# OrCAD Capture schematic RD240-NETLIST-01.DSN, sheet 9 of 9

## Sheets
9 1: size A3
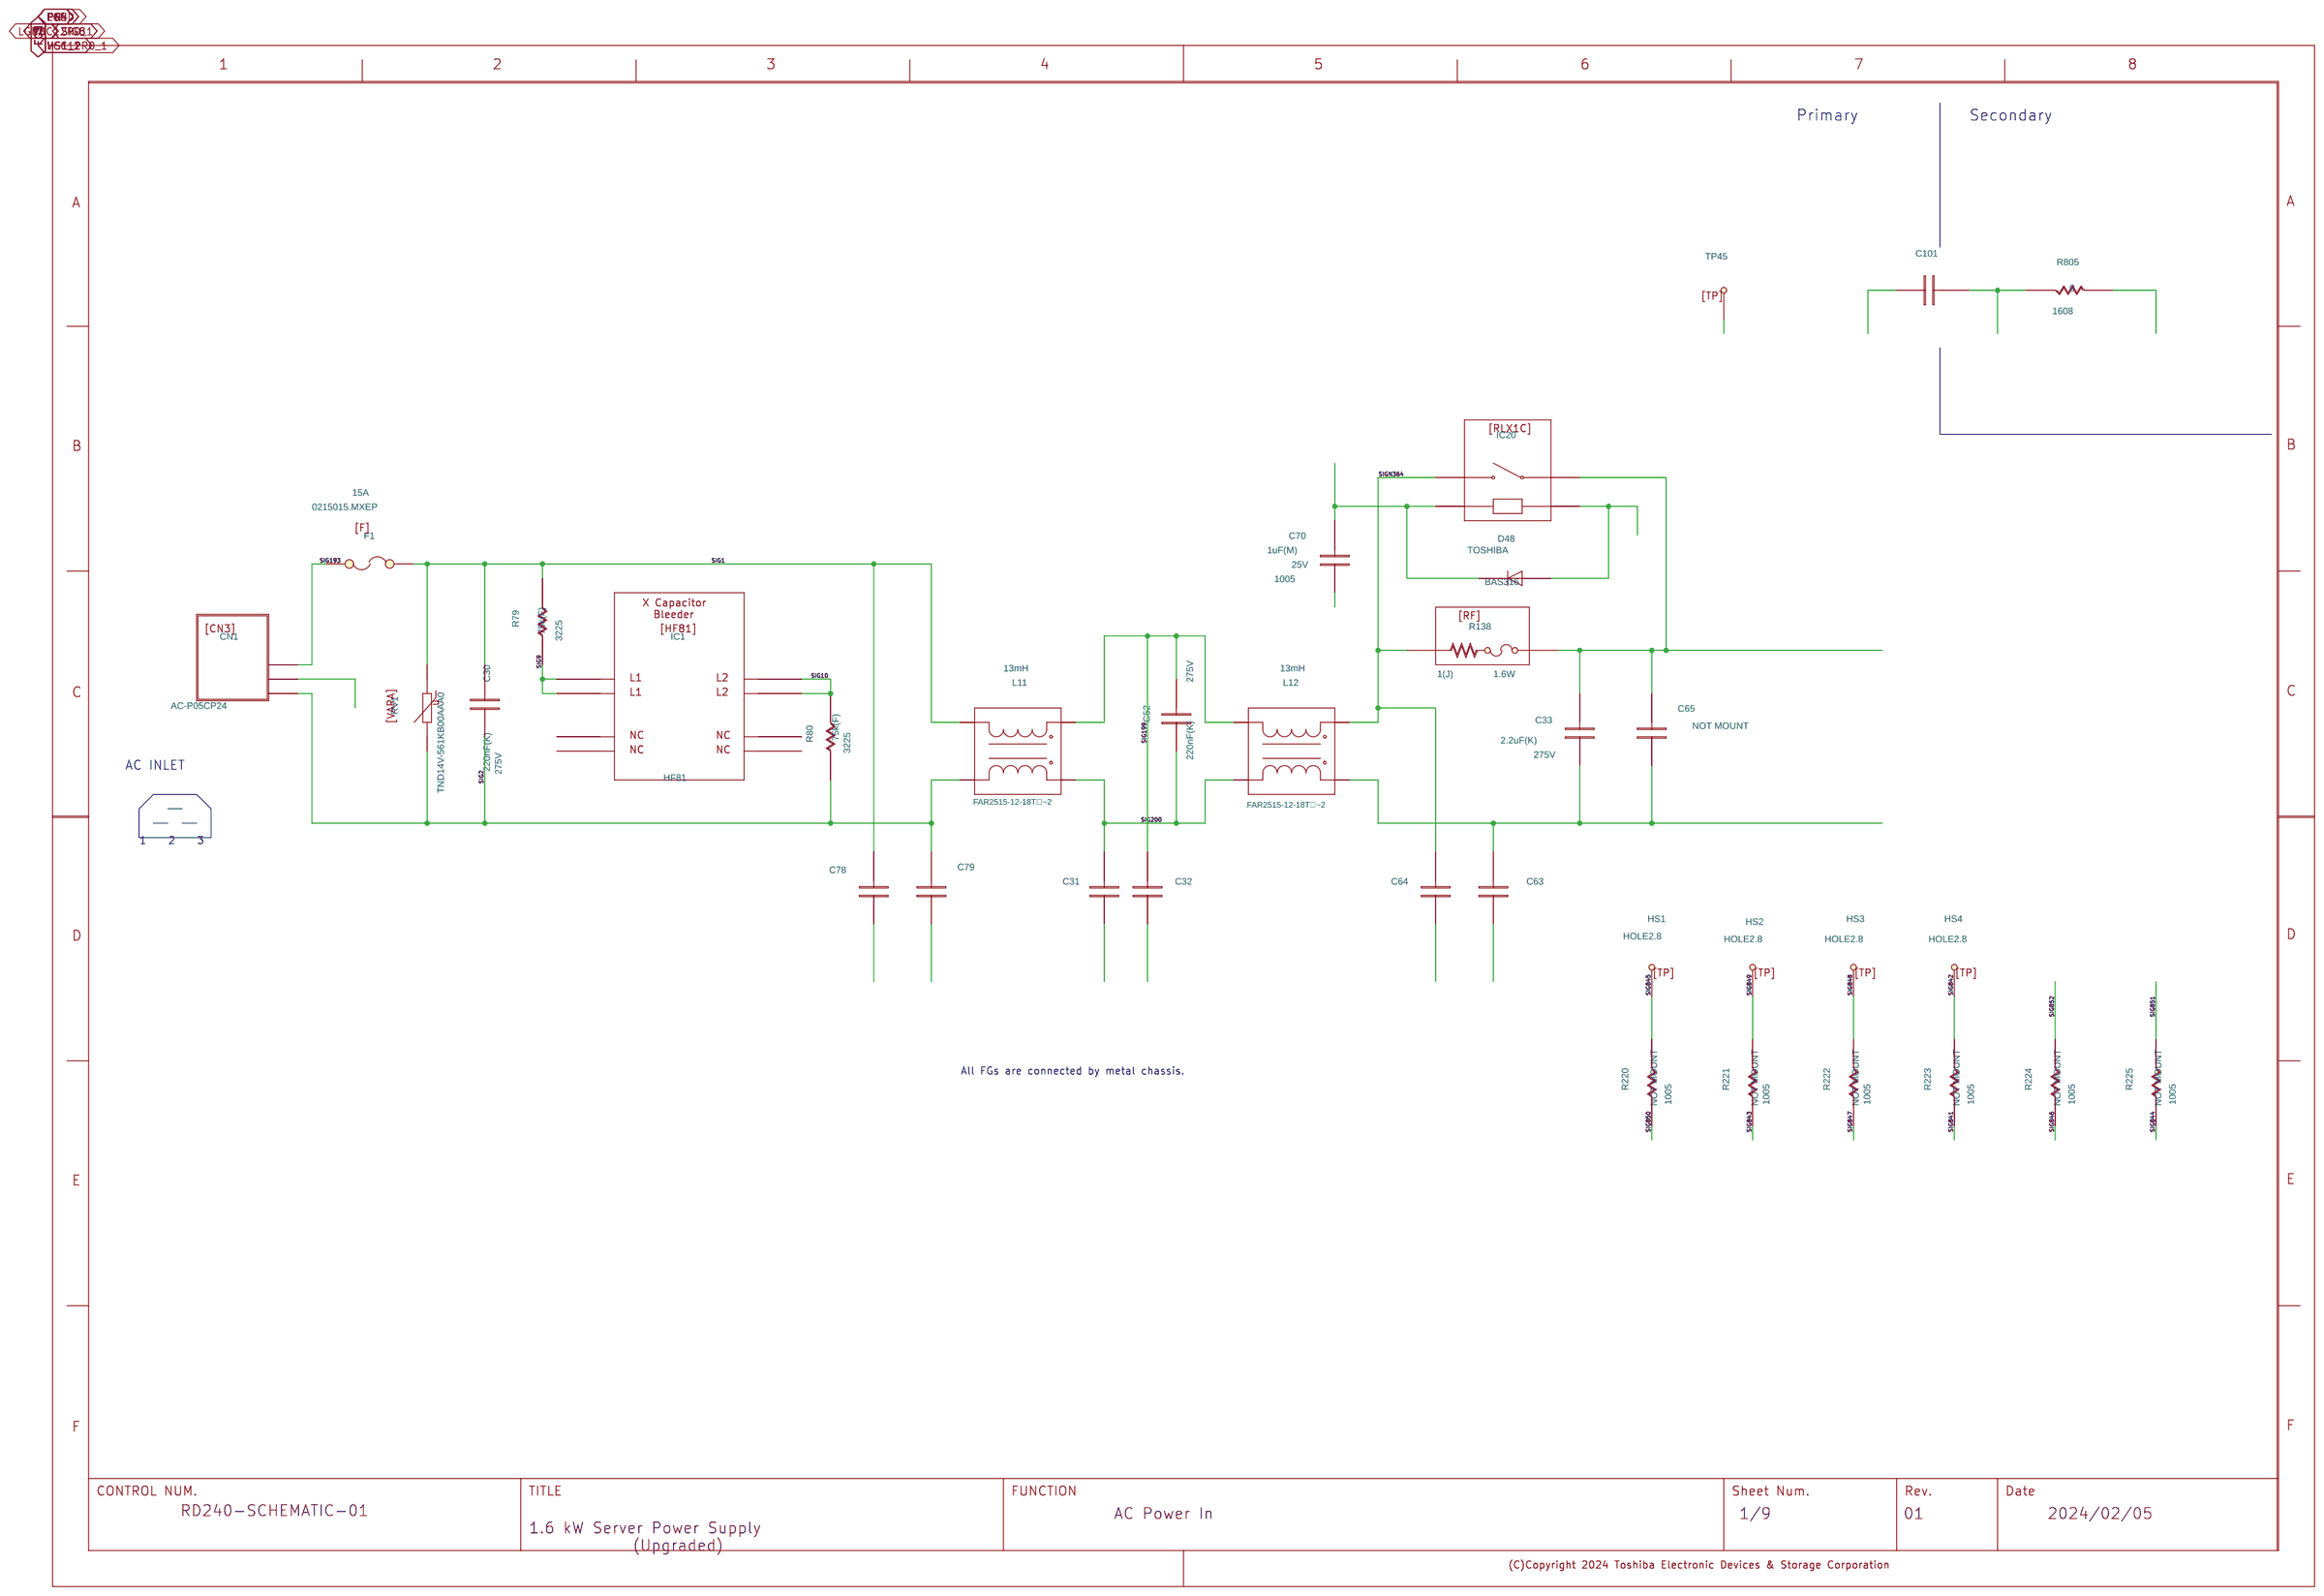
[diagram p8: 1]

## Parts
C30  C
C31  DE2E3SA222MN3AT02F
C32  DE2E3SA222MN3AT02F
C33  C
C52  C
C63  DE2E3SA222MN3AT02F
C64  DE2E3SA222MN3AT02F
C65  C
C70  C
C78  DE2B3SA101KA3BT02F
C79  DE2B3SA101KA3BT02F
C101  DE2B3SA221KA3BT02F
CN1  CN3
D48  D
F1  F
HS1  TP
HS2  TP
HS3  TP
HS4  TP
IC1  L81
IC20  G5PZ_1A
L11  HM_DLWHN6702
L12  HM_DLWHN6702
R79  R
R80  R
R138  A5MC_100JK_L3_5
R220  R
R221  R
R222  R
R223  R
R224  R
R225  R
R805  R
RV1  VARA
TP45  TP
U?#8  WAKU_DEF100

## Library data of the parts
C30 = C: AUTHOR: sptcae13; CAPACITANCETOLE: M; COMP: PRT_17; COMPONENTTYPE: 4; DATE: 2024/01/31; FNLEADFREETHET1GT2GMCTH1: N_N_N; GCOUNT: 1; INSTANCENAME: cmp241; MAKER: OKAYA; MAXGCOUNT: 1; NOMINALCAPACITA: 220n; OUMECLASSIFICATION: ƒtƒBƒ‹ƒƒRƒ“ƒfƒ“ƒT; OUMEMAKER: NIS ƒjƒbƒZƒC“d‹@; OUMEMAKERKATAMEI: R40KI322000**M; QUADMODEL: CON_220N; RATEDVOLTAGE: 275; SAVECOUNT: 0; SIZECODESMD: DIP; TIME: 13:58:26; UPDATEDATE: 2024/01/31; UPDATETIME: 13:58:26; UPDATEUSER: sptcae13; VAL1: 220nF(K); VAL2: 275V; VAL3: LE224-M
C31 = DE2E3SA222MN3AT02F: ADSMODELNAME: s_DE2E3KY222MN3AM02F; ALLGREEN: N:¢²¸; CAPACITANCETOLE: M; CDMASTERCADCELG: SIK0018; CHIPSIZE: [hsb`7.5mmió]; COMPONENTTYPE: 4; FNAPPROVALRESUG: 0:”­”Ô‚Ì‚Ý; FNCANCELLATIONG: 0:Žg—p‰Â; FNENVIRONMANTRG: N:¢²¸; FNLEADFREETHET1GT2GMCTH1: N_N_N; GCOUNT: 1; INSTANCENAME: cmp205; MAKER: MURATA; MAXGCOUNT: 1; NOMINALCAPACITA: 2.2n; OUMECLASSIFICATION: ƒZƒ‰ƒ~ƒbƒNƒRƒ“ƒfƒ“ƒT; OUMEMAKER: MRT ºc»ì; OUMEMAKERKATAMEI: DE2E3KY222MN3AM02F; OUMEPARTTYPE: C; PMPRODUCTSTYPEG: PC1; QUADMODEL: CON_2.2N; RATEDVOLTAGE: 250; SIZECODESMD: DIP; TEMPCHARACTERI2: E
C32 = DE2E3SA222MN3AT02F: ADSCNVFLAG: ON; ADSMODELNAME: s_DE2E3KY222MN3AM02F; ALLGREEN: N:¢²¸; CAPACITANCETOLE: M; CDMASTERCADCELG: SIK0018; CHIPSIZE: [hsb`7.5mmió]; COMPONENTTYPE: 4; FNAPPROVALRESUG: 0:”­”Ô‚Ì‚Ý; FNCANCELLATIONG: 0:Žg—p‰Â; FNENVIRONMANTRG: N:¢²¸; FNLEADFREETHET1GT2GMCTH1: N_N_N; GCOUNT: 1; ICX_PART_MODEL: CON_2.2N; INSTANCENAME: cmp206; MAKER: MURATA; MAXGCOUNT: 1; NOMINALCAPACITA: 2.2n; OUMECLASSIFICATION: ƒZƒ‰ƒ~ƒbƒNƒRƒ“ƒfƒ“ƒT; OUMEMAKER: MRT ºc»ì; OUMEMAKERKATAMEI: DE2E3KY222MN3AM02F; OUMEPARTTYPE: C; PMPRODUCTSTYPEG: PC1; QUADMODEL: CON_2.2N; RATEDVOLTAGE: 250; SIZECODESMD: DIP; SQ_PART_MODEL: CON_2.2N; TEMPCHARACTERI2: E
C33 = C: AUTHOR: sptcae13; CAPACITANCETOLE: K; CDMASTERCADCELG: DC0511; COMP: PRT_18; COMPONENTTYPE: 4; DATE: 2024/01/31; FNLEADFREETHET1GT2GMCTH1: 9_N_N; GCOUNT: 1; INSTANCENAME: cmp210; MAKER: Wurth; MAXGCOUNT: 1; NOMINALCAPACITA: 2.2u; OUMECLASSIFICATION: ƒtƒBƒ‹ƒƒRƒ“ƒfƒ“ƒT; OUMEMAKER: CHM “ú–{ƒPƒ~ƒRƒ“; OUMEMAKERKATAMEI: TACB2E225K; QUADMODEL: CON_2.2U; RATEDVOLTAGE: 250; SAVECOUNT: 0; SIZECODESMD: DIP; TIME: 13:58:26; UPDATEDATE: 2024/01/31; UPDATETIME: 13:58:26; UPDATEUSER: sptcae13; VAL1: 2.2uF(K); VAL2: 275V; VAL3: 890324026034CS
C52 = C: AUTHOR: sptcae13; CAPACITANCETOLE: M; COMP: PRT_17; COMPONENTTYPE: 4; DATE: 2024/01/31; FNLEADFREETHET1GT2GMCTH1: N_N_N; GCOUNT: 1; INSTANCENAME: cmp207; MAKER: OKAYA; MAXGCOUNT: 1; NOMINALCAPACITA: 220n; OUMECLASSIFICATION: ƒtƒBƒ‹ƒƒRƒ“ƒfƒ“ƒT; OUMEMAKER: NIS ƒjƒbƒZƒC“d‹@; OUMEMAKERKATAMEI: R40KI322000**M; QUADMODEL: CON_220N; RATEDVOLTAGE: 275; SAVECOUNT: 0; SIZECODESMD: DIP; TIME: 13:58:26; UPDATEDATE: 2024/01/31; UPDATETIME: 13:58:26; UPDATEUSER: sptcae13; VAL1: 220nF(K); VAL2: 275V; VAL3: LE224-M
C63 = DE2E3SA222MN3AT02F: ADSMODELNAME: s_DE2E3KY222MN3AM02F; ALLGREEN: N:¢²¸; CAPACITANCETOLE: M; CDMASTERCADCELG: SIK0018; CHIPSIZE: [hsb`7.5mmió]; COMPONENTTYPE: 4; FNAPPROVALRESUG: 0:”­”Ô‚Ì‚Ý; FNCANCELLATIONG: 0:Žg—p‰Â; FNENVIRONMANTRG: N:¢²¸; FNLEADFREETHET1GT2GMCTH1: N_N_N; GCOUNT: 1; INSTANCENAME: cmp208; MAKER: MURATA; MAXGCOUNT: 1; NOMINALCAPACITA: 2.2n; OUMECLASSIFICATION: ƒZƒ‰ƒ~ƒbƒNƒRƒ“ƒfƒ“ƒT; OUMEMAKER: MRT ºc»ì; OUMEMAKERKATAMEI: DE2E3KY222MN3AM02F; OUMEPARTTYPE: C; PMPRODUCTSTYPEG: PC1; QUADMODEL: CON_2.2N; RATEDVOLTAGE: 250; SIZECODESMD: DIP; TEMPCHARACTERI2: E
C64 = DE2E3SA222MN3AT02F: ADSMODELNAME: s_DE2E3KY222MN3AM02F; ALLGREEN: N:¢²¸; CAPACITANCETOLE: M; CDMASTERCADCELG: SIK0018; CHIPSIZE: [hsb`7.5mmió]; COMPONENTTYPE: 4; FNAPPROVALRESUG: 0:”­”Ô‚Ì‚Ý; FNCANCELLATIONG: 0:Žg—p‰Â; FNENVIRONMANTRG: N:¢²¸; FNLEADFREETHET1GT2GMCTH1: N_N_N; GCOUNT: 1; INSTANCENAME: cmp209; MAKER: MURATA; MAXGCOUNT: 1; NOMINALCAPACITA: 2.2n; OUMECLASSIFICATION: ƒZƒ‰ƒ~ƒbƒNƒRƒ“ƒfƒ“ƒT; OUMEMAKER: MRT ºc»ì; OUMEMAKERKATAMEI: DE2E3KY222MN3AM02F; OUMEPARTTYPE: C; PMPRODUCTSTYPEG: PC1; QUADMODEL: CON_2.2N; RATEDVOLTAGE: 250; SIZECODESMD: DIP; TEMPCHARACTERI2: E
C65 = C: AUTHOR: sptcae13; CAPACITANCETOLE: K; CDMASTERCADCELG: DC0511; COMP: PRT_18; COMPONENTTYPE: 4; DATE: 2024/01/31; FNLEADFREETHET1GT2GMCTH1: 9_N_N; GCOUNT: 1; INSTANCENAME: cmp211; MAKER: Wurth; MAXGCOUNT: 1; NOMINALCAPACITA: 2.2u; NOTMOUNT: NOT MOUNT; OUMECLASSIFICATION: ƒtƒBƒ‹ƒƒRƒ“ƒfƒ“ƒT; OUMEMAKER: CHM “ú–{ƒPƒ~ƒRƒ“; OUMEMAKERKATAMEI: TACB2E225K; QUADMODEL: CON_2.2U; RATEDVOLTAGE: 250; SAVECOUNT: 0; SIZECODESMD: DIP; TIME: 13:58:26; UPDATEDATE: 2024/01/31; UPDATETIME: 13:58:26; UPDATEUSER: sptcae13; VAL1: 2.2uF[K]; VAL2: 275V; VAL3: 890324026034CS
C70 = C: ADSMODELNAME: s_GRM155B31E105KA12D; AUTHOR: sptcae13; CAPACITANCETOLE: K; CDMASTERCADCELG: KC0005; CHIPSIZE: 1005; COMP: PRT_52; COMPONENTTYPE: 4; DATE: 2024/01/31; FNLEADFREETHET1GT2GMCTH1: 3_0_N; GCOUNT: 1; INSTANCENAME: cmp216; MAKER: TDK; MAXGCOUNT: 1; NOMINALCAPACITA: 1u; OUMECLASSIFICATION: ƒZƒ‰ƒ~ƒbƒNƒRƒ“ƒfƒ“ƒT; OUMEMAKER: MRT ºc»ì; OUMEMAKERKATAMEI: GRM155B31E105KA12D; PMPRODUCTSTYPEG: HD1; QUADMODEL: CON_1U; RATEDVOLTAGE: 25; SAVECOUNT: 0; SIZECODESMD: 1005; TEMPCHARACTERI2: B; TIME: 13:58:26; UPDATEDATE: 2024/01/31; UPDATETIME: 13:58:26; UPDATEUSER: sptcae13; VAL1: 1uF(M); VAL2: 25V; VAL3: C1005X5R1E105M050BC
C78 = DE2B3SA101KA3BT02F: ADSMODELNAME: s_DE2E3KY222MN3AM02F; ALLGREEN: N:¢²¸; CAPACITANCETOLE: M; CDMASTERCADCELG: SIK0018; CHIPSIZE: [hsb`7.5mmió]; COMPONENTTYPE: 4; FNAPPROVALRESUG: 0:”­”Ô‚Ì‚Ý; FNCANCELLATIONG: 0:Žg—p‰Â; FNENVIRONMANTRG: N:¢²¸; FNLEADFREETHET1GT2GMCTH1: N_N_N; GCOUNT: 1; INSTANCENAME: cmp203; MAKER: MURATA; MAXGCOUNT: 1; NOMINALCAPACITA: 2.2n; OUMECLASSIFICATION: ƒZƒ‰ƒ~ƒbƒNƒRƒ“ƒfƒ“ƒT; OUMEMAKER: MRT ºc»ì; OUMEMAKERKATAMEI: DE2E3KY222MN3AM02F; OUMEPARTTYPE: C; PMPRODUCTSTYPEG: PC1; QUADMODEL: CON_2.2N; RATEDVOLTAGE: 250; SIZECODESMD: DIP; TEMPCHARACTERI2: E
C79 = DE2B3SA101KA3BT02F: ADSMODELNAME: s_DE2E3KY222MN3AM02F; ALLGREEN: N:¢²¸; CAPACITANCETOLE: M; CDMASTERCADCELG: SIK0018; CHIPSIZE: [hsb`7.5mmió]; COMPONENTTYPE: 4; FNAPPROVALRESUG: 0:”­”Ô‚Ì‚Ý; FNCANCELLATIONG: 0:Žg—p‰Â; FNENVIRONMANTRG: N:¢²¸; FNLEADFREETHET1GT2GMCTH1: N_N_N; GCOUNT: 1; INSTANCENAME: cmp204; MAKER: MURATA; MAXGCOUNT: 1; NOMINALCAPACITA: 2.2n; OUMECLASSIFICATION: ƒZƒ‰ƒ~ƒbƒNƒRƒ“ƒfƒ“ƒT; OUMEMAKER: MRT ºc»ì; OUMEMAKERKATAMEI: DE2E3KY222MN3AM02F; OUMEPARTTYPE: C; PMPRODUCTSTYPEG: PC1; QUADMODEL: CON_2.2N; RATEDVOLTAGE: 250; SIZECODESMD: DIP; TEMPCHARACTERI2: E
C101 = DE2B3SA221KA3BT02F: ADSMODELNAME: s_DE2E3KY222MN3AM02F; ALLGREEN: N:¢²¸; CAPACITANCETOLE: M; CDMASTERCADCELG: SIK0018; COMPONENTTYPE: 4; FNAPPROVALRESUG: 0:”­”Ô‚Ì‚Ý; FNCANCELLATIONG: 0:Žg—p‰Â; FNENVIRONMANTRG: N:¢²¸; FNLEADFREETHET1GT2GMCTH1: N_N_N; GCOUNT: 1; INSTANCENAME: cmp215; MAKER: MURATA; MAXGCOUNT: 1; NOMINALCAPACITA: 2.2n; OUMECLASSIFICATION: ƒZƒ‰ƒ~ƒbƒNƒRƒ“ƒfƒ“ƒT; OUMEMAKER: MRT ºc»ì; OUMEMAKERKATAMEI: DE2E3KY222MN3AM02F; OUMEPARTTYPE: C; PMPRODUCTSTYPEG: PC1; QUADMODEL: CON_2.2N; RATEDVOLTAGE: 250; SIZECODESMD: DIP; TEMPCHARACTERI2: E
CN1 = CN3: AUTHOR: sptcae13; COMP: PRT_61; COMPONENTTYPE: 4; DATE: 2024/01/31; INSTANCENAME: cmp181; MAKER: ECHO ELECTRIC; SAVECOUNT: 0; TIME: 13:58:26; UPDATEDATE: 2024/01/31; UPDATETIME: 13:58:26; UPDATEUSER: sptcae13; VAL1: 15A; VAL2: 250V; VAL3: AC-P05CP24
D48 = D: ADSMODELNAME: s_BAS16_02W; AUTHOR: sptcae13; CDMASTERCADCELG: D8101D; COMP: PRT_26; COMPONENTTYPE: 4; DATE: 2024/01/31; FNLEADFREETHET1GT2GMCTH1: N_N_N; FORWARDVOLTAGEM: 0; GCOUNT: 1; INSTANCENAME: cmp96; MAKER: TOSHIBA; MAXAVERAGEFORWA: 0; MAXGCOUNT: 1; MAXREPETITIVEPE: 0; MAXREVERSEVOLTA: 0; MOUNTINGFORMSMD: SMD; OUMECLASSIFICATION: »Ì¼_CI[h; OUMEMAKER: IFO CtBjIeNmW[Y; OUMEMAKERKATAMEI: BAS16-02W; PEAKFORWARDVOLT: 0; REVERSECURRENT: 0; TIME: 13:58:26; UPDATEDATE: 2024/01/31; UPDATETIME: 13:58:26; UPDATEUSER: sptcae13; USERCOMPTEXT3: TOSHIBA; VAL3: BAS316; ZENERVOLTAGEMAX: 0; ZENERVOLTAGEMIN: 0
F1 = F: AUTHOR: sptcae13; COMP: PRT_21; COMPONENTTYPE: 4; DATE: 2024/01/31; GCOUNT: 1; INSTANCENAME: cmp3; MAKER: Littelfuse; MAXGCOUNT: 1; MOUNTINGFORMSMD: SMD; NOMINALOPERATIO: 0; RATEDINTERRUPTI: 0; RATEDVOLTAGE: 0; SAVECOUNT: 0; TIME: 13:58:25; UPDATEDATE: 2024/01/31; UPDATETIME: 13:58:25; UPDATEUSER: sptcae13; VAL1: 15A; VAL3: 0215015.MXEP
HS1 = TP: AUTHOR: sptcae13; CHIPSIZE: Through Hole; COMP: PRT_39; COMPONENTTYPE: 4; DATE: 2024/01/31; INSTANCENAME: cmp161; TIME: 13:58:25; UPDATEDATE: 2024/01/31; UPDATETIME: 13:58:25; UPDATEUSER: sptcae13; VAL3: HOLE2.8
HS2 = TP: AUTHOR: sptcae13; CHIPSIZE: Through Hole; COMP: PRT_39; COMPONENTTYPE: 4; DATE: 2024/01/31; INSTANCENAME: cmp162; TIME: 13:58:25; UPDATEDATE: 2024/01/31; UPDATETIME: 13:58:25; UPDATEUSER: sptcae13; VAL3: HOLE2.8
HS3 = TP: AUTHOR: sptcae13; CHIPSIZE: Through Hole; COMP: PRT_39; COMPONENTTYPE: 4; DATE: 2024/01/31; INSTANCENAME: cmp163; TIME: 13:58:25; UPDATEDATE: 2024/01/31; UPDATETIME: 13:58:25; UPDATEUSER: sptcae13; VAL3: HOLE2.8
HS4 = TP: AUTHOR: sptcae13; CHIPSIZE: Through Hole; COMP: PRT_39; COMPONENTTYPE: 4; DATE: 2024/01/31; INSTANCENAME: cmp164; TIME: 13:58:25; UPDATEDATE: 2024/01/31; UPDATETIME: 13:58:25; UPDATEUSER: sptcae13; VAL3: HOLE2.8
IC1 = L81: COMP: PRT_45; COMPONENTTYPE: 4; INSTANCENAME: cmp19; MAKER: MPS; VAL3: HF81
IC20 = G5PZ_1A: COMPONENTTYPE: 4; FUNCN: G5PZ-1A; GCOUNT: 1; INSTANCENAME: cmp94; MAKER: PANASONIC; MAXGCOUNT: 1
L11 = HM_DLWHN6702: COMP: PRT_22; COMPONENTTYPE: 4; INSTANCENAME: cmp102; MAKER: NEC TOKIN; VAL1: 13mH; VAL3: FAR2515-12-18T~2
L12 = HM_DLWHN6702: COMP: PRT_22; COMPONENTTYPE: 4; INSTANCENAME: cmp103; MAKER: NEC TOKIN; VAL1: 13mH; VAL3: FAR2515-12-18T~2
R79 = R: ADSMODELNAME: s_RK73H2ETE563F; CDMASTERCADCELG: DR903A; CHIPSIZE: 3225; COMPONENTTYPE: 4; FNLEADFREETHET1GT2GMCTH1: N_N_N; GCOUNT: 1; INSTANCENAME: cmp201; MAKER: PANASONIC; MAXGCOUNT: 1; MOUNTINGFORMSMD: SMD; NOMINALRESISTAN: 56K; OUMECLASSIFICATION: \ÊÀpÅèïRí; OUMEMAKER: KOA R[A; OUMEMAKERKATAMEI: RK73H2ETE563F; POWERRATING: 250m; QUADMODEL: RES_56K; RESISTANCETOLER: F; SAVEAREA0: -588,-4192,15498,7584; SAVECOUNT: 0; SIZECODESMD: 3225; UPDATETIME: 09:21:07; VAL1: 75k(F); VAL2: 500mW; VAL3: ERJ-14NF7502U
R80 = R: ADSMODELNAME: s_RK73H2ETE563F; CDMASTERCADCELG: DR903A; CHIPSIZE: 3225; COMPONENTTYPE: 4; FNLEADFREETHET1GT2GMCTH1: N_N_N; GCOUNT: 1; INSTANCENAME: cmp202; MAKER: PANASONIC; MAXGCOUNT: 1; MOUNTINGFORMSMD: SMD; NOMINALRESISTAN: 56K; OUMECLASSIFICATION: \ÊÀpÅèïRí; OUMEMAKER: KOA R[A; OUMEMAKERKATAMEI: RK73H2ETE563F; POWERRATING: 250m; QUADMODEL: RES_56K; RESISTANCETOLER: F; SAVEAREA0: -588,-4192,15498,7584; SAVECOUNT: 0; SIZECODESMD: 3225; UPDATETIME: 09:21:07; VAL1: 75k(F); VAL2: 500mW; VAL3: ERJ-14NF7502U
R138 = A5MC_100JK_L3_5: ALLGREEN: 1:ñO[; CDMASTERCADCELG: DR0127; CHIPSIZE: 13x9xH25.5; COMPONENTTYPE: 4; FNAPPROVALRESUG: 4:i; FNCANCELLATIONG: 0:Žg—p‰Â; FNENVIRONMANTRG: N:¢²¸; FNLEADFREETHET1GT2GMCTH1: 9_N_N; FUNCN: A5MC-100JK_L3_5; GCOUNT: 1; INSTANCENAME: cmp161; MAKER: TAKMAN; MAXGCOUNT: 1; MOUNTINGFORMSMD: DIP; NOMINALRESISTAN: 1; NUMBEROFELEMENT: 0; OUMECLASSIFICATION: q[YïRí; OUMEMAKER: MIC ~NdC; OUMEMAKERKATAMEI: MEG05N1R0JB135; OUMEPARTTYPE: R; POWERRATING: 1.6; QUADMODEL: RES_1; RESISTANCETOLER: J; VAL1: 1(J); VAL2: 1.6W
R220 = R: ADSCNVFLAG: ON; ADSCOMPONENTNAME: R_1005; ADSMODELNAME: s_CR10_000V; CDMASTERCADCELG: KC0005; CHIPSIZE: 1608; COMPONENTTYPE: 4; FNLEADFREETHET1GT2GMCTH1: N_N_N; GCOUNT: 1; ICX_PART_MODEL: RES_0; INSTANCENAME: cmp169; MAKER: KOA; MAXGCOUNT: 1; MOUNTINGFORMSMD: SMD; NOMINALRESISTAN: 0; NOTMOUNT: NOT MOUNT; OUMECLASSIFICATION: \ÊÀpÅèïRí; OUMEMAKER: HDK k¤dCHÆ; OUMEMAKERKATAMEI: CR10-000V; POWERRATING: 63m; QUADMODEL: RES_0; RESISTANCETOLER: X; SAVECOUNT: 0; SIZECODESMD: 1005; SQ_PART_MODEL: RES_0; VAL1: 0; VAL2: 63mW; VAL3: RK73Z1ETTP
R221 = R: ADSCNVFLAG: ON; ADSCOMPONENTNAME: R_1005; ADSMODELNAME: s_CR10_000V; CDMASTERCADCELG: KC0005; CHIPSIZE: 1608; COMPONENTTYPE: 4; FNLEADFREETHET1GT2GMCTH1: N_N_N; GCOUNT: 1; ICX_PART_MODEL: RES_0; INSTANCENAME: cmp170; MAKER: KOA; MAXGCOUNT: 1; MOUNTINGFORMSMD: SMD; NOMINALRESISTAN: 0; NOTMOUNT: NOT MOUNT; OUMECLASSIFICATION: \ÊÀpÅèïRí; OUMEMAKER: HDK k¤dCHÆ; OUMEMAKERKATAMEI: CR10-000V; POWERRATING: 63m; QUADMODEL: RES_0; RESISTANCETOLER: X; SAVECOUNT: 0; SIZECODESMD: 1005; SQ_PART_MODEL: RES_0; VAL1: 0; VAL2: 63mW; VAL3: RK73Z1ETTP
R222 = R: ADSCNVFLAG: ON; ADSCOMPONENTNAME: R_1005; ADSMODELNAME: s_CR10_000V; CDMASTERCADCELG: KC0005; CHIPSIZE: 1608; COMPONENTTYPE: 4; FNLEADFREETHET1GT2GMCTH1: N_N_N; GCOUNT: 1; ICX_PART_MODEL: RES_0; INSTANCENAME: cmp171; MAKER: KOA; MAXGCOUNT: 1; MOUNTINGFORMSMD: SMD; NOMINALRESISTAN: 0; NOTMOUNT: NOT MOUNT; OUMECLASSIFICATION: \ÊÀpÅèïRí; OUMEMAKER: HDK k¤dCHÆ; OUMEMAKERKATAMEI: CR10-000V; POWERRATING: 63m; QUADMODEL: RES_0; RESISTANCETOLER: X; SAVECOUNT: 0; SIZECODESMD: 1005; SQ_PART_MODEL: RES_0; VAL1: 0; VAL2: 63mW; VAL3: RK73Z1ETTP
R223 = R: ADSCNVFLAG: ON; ADSCOMPONENTNAME: R_1005; ADSMODELNAME: s_CR10_000V; CDMASTERCADCELG: KC0005; CHIPSIZE: 1608; COMPONENTTYPE: 4; FNLEADFREETHET1GT2GMCTH1: N_N_N; GCOUNT: 1; ICX_PART_MODEL: RES_0; INSTANCENAME: cmp172; MAKER: KOA; MAXGCOUNT: 1; MOUNTINGFORMSMD: SMD; NOMINALRESISTAN: 0; NOTMOUNT: NOT MOUNT; OUMECLASSIFICATION: \ÊÀpÅèïRí; OUMEMAKER: HDK k¤dCHÆ; OUMEMAKERKATAMEI: CR10-000V; POWERRATING: 63m; QUADMODEL: RES_0; RESISTANCETOLER: X; SAVECOUNT: 0; SIZECODESMD: 1005; SQ_PART_MODEL: RES_0; VAL1: 0; VAL2: 63mW; VAL3: RK73Z1ETTP
R224 = R: ADSCNVFLAG: ON; ADSCOMPONENTNAME: R_1005; ADSMODELNAME: s_CR10_000V; CDMASTERCADCELG: KC0005; CHIPSIZE: 1608; COMPONENTTYPE: 4; FNLEADFREETHET1GT2GMCTH1: N_N_N; GCOUNT: 1; ICX_PART_MODEL: RES_0; INSTANCENAME: cmp177; MAKER: KOA; MAXGCOUNT: 1; MOUNTINGFORMSMD: SMD; NOMINALRESISTAN: 0; NOTMOUNT: NOT MOUNT; OUMECLASSIFICATION: \ÊÀpÅèïRí; OUMEMAKER: HDK k¤dCHÆ; OUMEMAKERKATAMEI: CR10-000V; POWERRATING: 63m; QUADMODEL: RES_0; RESISTANCETOLER: X; SAVECOUNT: 0; SIZECODESMD: 1005; SQ_PART_MODEL: RES_0; VAL1: 0; VAL2: 63mW; VAL3: RK73Z1ETTP
R225 = R: ADSCNVFLAG: ON; ADSCOMPONENTNAME: R_1005; ADSMODELNAME: s_CR10_000V; CDMASTERCADCELG: KC0005; CHIPSIZE: 1608; COMPONENTTYPE: 4; FNLEADFREETHET1GT2GMCTH1: N_N_N; GCOUNT: 1; ICX_PART_MODEL: RES_0; INSTANCENAME: cmp178; MAKER: KOA; MAXGCOUNT: 1; MOUNTINGFORMSMD: SMD; NOMINALRESISTAN: 0; NOTMOUNT: NOT MOUNT; OUMECLASSIFICATION: \ÊÀpÅèïRí; OUMEMAKER: HDK k¤dCHÆ; OUMEMAKERKATAMEI: CR10-000V; POWERRATING: 63m; QUADMODEL: RES_0; RESISTANCETOLER: X; SAVECOUNT: 0; SIZECODESMD: 1005; SQ_PART_MODEL: RES_0; VAL1: 0; VAL2: 63mW; VAL3: RK73Z1ETTP
R805 = R: ADSMODELNAME: s_RK73Z1JTTD; CDMASTERCADCELG: KCK0203; CHIPSIZE: 1608; COMPONENTTYPE: 4; FNLEADFREETHET1GT2GMCTH1: 3_2_N; GCOUNT: 1; INSTANCENAME: cmp239; MAKER: KOA; MAXGCOUNT: 1; MOUNTINGFORMSMD: SMD; NOMINALRESISTAN: 0; OUMECLASSIFICATION: \ÊÀpÅèïRí; OUMEMAKER: KOA R[A; OUMEMAKERKATAMEI: RK73Z1JTTD; PMPRODUCTSTYPEG: DME-HD1-PC1; POWERRATING: 100m; QUADMODEL: RES_0; RESISTANCETOLER: X; SAVEAREA0: -588,-4192,15498,7584; SAVECOUNT: 0; SIZECODESMD: 1608; UPDATETIME: 09:21:07; VAL1: 0; VAL2: 100mW; VAL3: RK73Z1JTTD
RV1 = VARA: AUTHOR: sptcae13; CDMASTERCADCELG: KC0008; COMP: PRT_37; COMPONENTTYPE: 4; DATE: 2024/01/31; FNLEADFREETHET1GT2GMCTH1: N_N_N; GCOUNT: 1; INSTANCENAME: cmp2; MAKER: NIPPON CHEMICON; MAXGCOUNT: 1; MOUNTINGFORMSMD: SMD; OUMECLASSIFICATION: ƒoƒŠƒXƒ^; OUMEMAKER: TDK ‚s‚c‚j; OUMEMAKERKATAMEI: AVR-M1608C220KT6AB; OUMEPARTTYPE: RV; RATEDVOLTAGE: 0; TIME: 13:58:25; UPDATEDATE: 2024/01/31; UPDATETIME: 13:58:25; UPDATEUSER: sptcae13; VAL1: 560V; VAL3: TND14V-561KB00AAA0
TP45 = TP: AUTHOR: sptcae13; COMP: PRT_49; COMPONENTTYPE: 4; DATE: 2024/01/31; INSTANCENAME: cmp191; MAKER: MAC8; TIME: 13:58:25; UPDATEDATE: 2024/01/31; UPDATETIME: 13:58:25; UPDATEUSER: sptcae13; VAL3: LC-22-S-WHITE
U?#8 = WAKU_DEF100: COMPONENTTYPE: 2; DATE: 2024/02/05; DESIGNED: TOSHIBA; DRAWINGNUMBER: RD240-SCHEMATIC-01; FUNCTION: AC Power In; INSTANCENAME: cmp235; PAGENUMBER: 1; REVISION: 01; SHEETNUMBER: 1/9; SHTSAVECOUNT: 38; TITLE: 1.6 kW Server Power Supply / (Upgraded); UPDATEDATE: 2024/02/07; UPDATETIME: 11:13:58; UPDATEUSER: t5459927

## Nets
VCC12R0_1: C70.2 D48.C IC20.4 ; also on sheet 2 6 7 8
FG1: CN1.2
FG2: C79.1
FG3: C32.1 C78.1
FG4: C31.1 C63.1 C64.1
FG5: C101.2 R805.2
HS1_1: R224.2
HS1_2: R225.2
LGND: R805.1 ; also on sheet 1 2 3 4 5 6
PN: C70.1 C101.1 D48.A IC20.1 R220.1 R221.1 R222.1 R223.1 R224.1 R225.1 TP45.1 ; also on sheet 2 3 6 7 8
SIG1: C30.2 C78.2 F1.2 L11.2 R79.2 RV1.1
SIG2: C30.1 C79.2 CN1.3 L11.3 R80.1 RV1.2
SIG6: C33.1 C63.2 C65.1 L12.4 ; also on sheet 8
SIG8: C33.2 C65.2 IC20.2 R138.2 ; also on sheet 8
SIG9: IC1.2 IC1.3 R79.1
SIG10: IC1.6 IC1.7 R80.2
SIG193: CN1.1 F1.1
SIG199: C32.2 C52.2 L11.1 L12.2
SIG200: C31.2 C52.1 L11.4 L12.3
SIG842: HS4.1 R223.2
SIG845: HS1.1 R220.2
SIG848: HS3.1 R222.2
SIG849: HS2.1 R221.2
SIGN364: C64.2 IC20.3 L12.1 R138.1

Not connected (* = marked no-connect by the designer): IC1 1 4 5 8

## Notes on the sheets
sheet 9
- Primary
- Secondary
- AC INLET
- 1
- 2
- 3
- All FGs are connected by metal chassis.
